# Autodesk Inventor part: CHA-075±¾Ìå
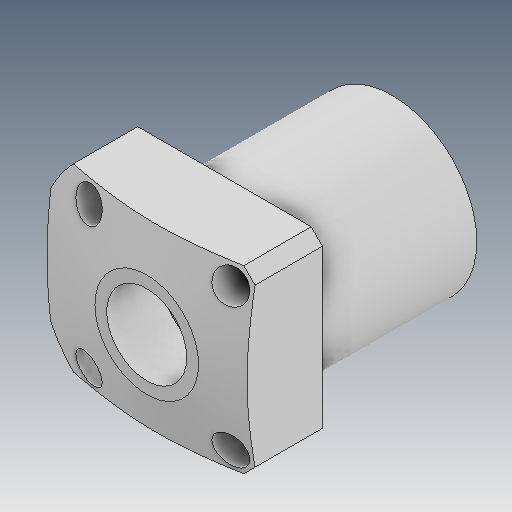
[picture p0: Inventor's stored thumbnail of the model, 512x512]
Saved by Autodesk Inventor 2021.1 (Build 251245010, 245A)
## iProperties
Created: 2019-12
Part Number: CHA-075±¾Ìå
Material: Ogólny
Document SubType Name: Modeling
Designer: user
Density: 1 g/cm^3
Appearance: Domyślna
Author: user
Revision Number: ÈÎºÎ
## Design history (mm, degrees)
feature "ÇÐ³ý-À­Éì7"
node "Bryła1"
